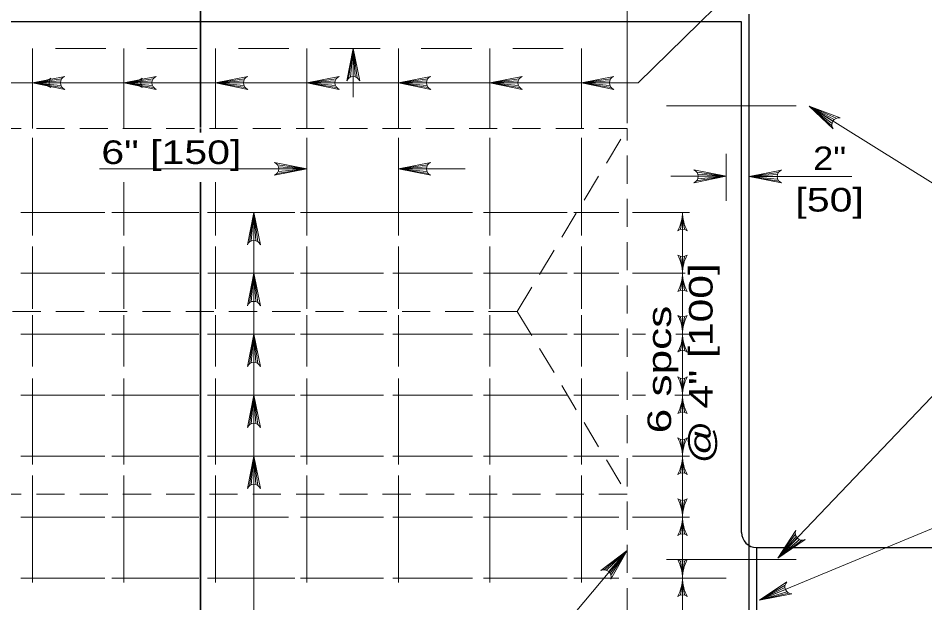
# Model space of a CAD drawing. Extents: x 758.3 to 792.3, y 849.7 to 893.7.
# Drawn here: x 771.26 to 777.25, y 887.19 to 891.06 of the extents above; entities that cross this region are included whole.
import ezdxf
from ezdxf.enums import TextEntityAlignment as Align

# ---------------------------------------------------------------- set-up
doc = ezdxf.new("R2010")
doc.units = 0
doc.header["$LTSCALE"] = 0.062
doc.linetypes.add('MEDIUM_DASHED', pattern=[4.5, 3, -1.5])
doc.layers.add('1', color=7, linetype='Continuous', lineweight=13)

msp = doc.modelspace()

# ---------------------------------------------------------------- linework, layer by layer
at = {"layer": '1', "lineweight": 35}
for p, q in [((772.46325, 891.62983), (772.46325, 890.33417)), ((772.46325, 890.32608), (772.46325, 890.30083)), ((772.46325, 889.97258), (772.46325, 889.61833))]:
    msp.add_line(p, q, dxfattribs=at)
at = {"layer": '1'}
for p, q in [((775.28242, 890.361), (775.28242, 891.18492)), ((771.35175, 890.32608), (771.35175, 890.85517)), ((771.50342, 890.85517), (771.83683, 890.85517)), ((771.9565, 890.32608), (771.9565, 890.85517)), ((772.10817, 890.85517), (772.44158, 890.85517)), ((772.56117, 890.32608), (772.56117, 890.85517)), ((772.71292, 890.85517), (773.04625, 890.85517)), ((773.16592, 890.32608), (773.16592, 890.85517)), ((773.31758, 890.85517), (773.651, 890.85517)), ((773.44208, 890.659), (773.47208, 890.85517)), ((773.45467, 890.66642), (773.47208, 890.85517)), ((773.47208, 890.535), (773.47208, 890.85517)), ((773.47208, 890.66983), (773.47208, 890.85517)), ((773.48583, 890.66783), (773.47208, 890.85517)), ((773.49925, 890.66125), (773.47208, 890.85517)), ((773.77067, 890.32608), (773.77067, 890.85517)), ((773.92233, 890.85517), (774.25575, 890.85517)), ((774.37533, 890.32608), (774.37533, 890.85517)), ((774.527, 890.85517), (774.86042, 890.85517)), ((774.98008, 890.32608), (774.98008, 890.85517)), ((775.35458, 890.62842), (770.14233, 890.62842)), ((771.54567, 890.65558), (771.35175, 890.62842)), ((771.53908, 890.64217), (771.35175, 890.62842)), ((771.53708, 890.62842), (771.35175, 890.62842)), ((771.5405, 890.611), (771.35175, 890.62842)), ((771.54792, 890.59842), (771.35175, 890.62842)), ((772.15042, 890.65558), (771.9565, 890.62842)), ((772.14383, 890.64217), (771.9565, 890.62842)), ((772.14183, 890.62842), (771.9565, 890.62842)), ((772.14525, 890.611), (771.9565, 890.62842)), ((772.15267, 890.59842), (771.9565, 890.62842)), ((772.75508, 890.65558), (772.56117, 890.62842)), ((772.7485, 890.64217), (772.56117, 890.62842)), ((772.7465, 890.62842), (772.56117, 890.62842)), ((772.74992, 890.611), (772.56117, 890.62842)), ((772.75742, 890.59842), (772.56117, 890.62842)), ((773.35983, 890.65558), (773.16592, 890.62842)), ((773.35325, 890.64217), (773.16592, 890.62842)), ((773.35125, 890.62842), (773.16592, 890.62842)), ((773.35467, 890.611), (773.16592, 890.62842)), ((773.36208, 890.59842), (773.16592, 890.62842)), ((773.9645, 890.65558), (773.77067, 890.62842)), ((773.95792, 890.64217), (773.77067, 890.62842)), ((773.95592, 890.62842), (773.77067, 890.62842)), ((773.95942, 890.611), (773.77067, 890.62842)), ((773.96683, 890.59842), (773.77067, 890.62842)), ((774.56925, 890.65558), (774.37533, 890.62842)), ((774.56267, 890.64217), (774.37533, 890.62842)), ((774.56067, 890.62842), (774.37533, 890.62842)), ((774.56408, 890.611), (774.37533, 890.62842)), ((774.5715, 890.59842), (774.37533, 890.62842)), ((775.17392, 890.65558), (774.98008, 890.62842)), ((775.16742, 890.64217), (774.98008, 890.62842)), ((775.16542, 890.62842), (774.98008, 890.62842)), ((775.16883, 890.611), (774.98008, 890.62842)), ((775.17625, 890.59842), (774.98008, 890.62842)), ((775.54233, 890.47725), (776.399, 890.47725)), ((776.64283, 890.37567), (776.48558, 890.47375)), ((776.63658, 890.35908), (776.48558, 890.47375)), ((776.63625, 890.3445), (776.48558, 890.47375)), ((776.65183, 890.38625), (776.48558, 890.47375)), ((776.6645, 890.39417), (776.48558, 890.47375)), ((771.35175, 889.61833), (771.35175, 890.265)), ((773.16592, 889.61833), (773.16592, 890.265)), ((773.77067, 889.61833), (773.77067, 890.265)), ((774.37533, 889.61833), (774.37533, 890.265)), ((774.98008, 889.61833), (774.98008, 890.265)), ((775.9375, 889.849), (775.9375, 890.15992)), ((771.79583, 890.05975), (773.16592, 890.05975)), ((772.96975, 890.02975), (773.16592, 890.05975)), ((772.972, 890.08692), (773.16592, 890.05975)), ((772.97717, 890.04233), (773.16592, 890.05975)), ((772.97858, 890.07342), (773.16592, 890.05975)), ((772.98058, 890.05975), (773.16592, 890.05975)), ((773.9645, 890.08692), (773.77067, 890.05975)), ((773.95792, 890.07342), (773.77067, 890.05975)), ((773.77067, 890.05975), (774.21117, 890.05975)), ((773.95592, 890.05975), (773.77067, 890.05975)), ((773.95942, 890.04233), (773.77067, 890.05975)), ((773.96683, 890.02975), (773.77067, 890.05975)), ((775.57142, 890.0105), (775.9375, 890.0105)), ((775.74133, 889.9805), (775.9375, 890.0105)), ((775.74367, 890.03758), (775.9375, 890.0105)), ((775.74875, 889.99308), (775.9375, 890.0105)), ((775.75017, 890.02417), (775.9375, 890.0105)), ((775.75217, 890.0105), (775.9375, 890.0105)), ((776.28258, 890.0365), (776.08867, 890.00933)), ((776.276, 890.02308), (776.08867, 890.00933)), ((776.08867, 890.00933), (776.76792, 890.00933)), ((776.274, 890.00933), (776.08867, 890.00933)), ((776.27742, 889.99192), (776.08867, 890.00933)), ((776.28492, 889.97942), (776.08867, 890.00933)), ((771.9565, 889.61833), (771.9565, 889.97258)), ((772.56117, 889.61833), (772.56117, 889.97258)), ((771.83008, 889.77183), (771.2755, 889.77183)), ((772.45125, 889.77183), (771.87758, 889.77183)), ((773.0865, 889.77183), (772.50808, 889.77183)), ((772.78558, 889.57567), (772.81558, 889.77183)), ((772.79817, 889.58308), (772.81558, 889.77183)), ((772.81558, 886.85167), (772.81558, 889.77183)), ((772.81558, 889.5865), (772.81558, 889.77183)), ((772.82925, 889.5845), (772.81558, 889.77183)), ((772.84275, 889.57792), (772.81558, 889.77183)), ((773.16592, 889.77183), (773.1235, 889.77183)), ((774.26117, 889.77183), (773.16592, 889.77183)), ((774.88692, 889.77183), (774.33233, 889.77183)), ((775.2285, 889.77183), (774.92967, 889.77183)), ((775.31867, 889.77183), (775.69467, 889.77183)), ((771.35175, 889.13333), (771.35175, 889.54533)), ((771.9565, 889.13333), (771.9565, 889.54533)), ((772.56117, 889.13333), (772.56117, 889.54533)), ((773.16592, 889.13333), (773.16592, 889.54533)), ((773.77067, 889.13333), (773.77067, 889.54533)), ((774.37533, 889.13333), (774.37533, 889.54533)), ((774.98008, 889.13333), (774.98008, 889.54533)), ((776.27875, 887.48392), (778.14217, 889.441)), ((771.83008, 889.36875), (771.2755, 889.36875)), ((772.45125, 889.36875), (771.87758, 889.36875)), ((773.08075, 889.36875), (772.51192, 889.36875)), ((772.78558, 889.17258), (772.81558, 889.36875)), ((772.79817, 889.18), (772.81558, 889.36875)), ((772.81558, 889.18342), (772.81558, 889.36875)), ((772.82925, 889.18142), (772.81558, 889.36875)), ((772.84275, 889.17483), (772.81558, 889.36875)), ((773.67333, 889.36875), (773.1235, 889.36875)), ((774.26117, 889.36875), (773.73492, 889.36875)), ((774.88692, 889.36875), (774.33233, 889.36875)), ((775.2285, 889.36875), (774.92967, 889.36875)), ((775.31867, 889.36875), (775.6655, 889.36875)), ((771.35175, 888.75258), (771.35175, 889.09167)), ((771.9565, 888.75258), (771.9565, 889.09167)), ((772.56117, 888.75258), (772.56117, 889.09167)), ((773.16592, 888.75258), (773.16592, 889.09167)), ((773.77067, 888.75258), (773.77067, 889.09167)), ((774.37533, 888.75258), (774.37533, 889.09167)), ((774.98008, 888.75258), (774.98008, 889.09167)), ((771.83008, 888.96567), (771.2755, 888.96567)), ((772.45125, 888.96567), (771.87758, 888.96567)), ((773.0865, 888.96567), (772.50808, 888.96567)), ((772.78558, 888.76942), (772.81558, 888.96567)), ((772.79817, 888.77692), (772.81558, 888.96567)), ((772.81558, 888.78033), (772.81558, 888.96567)), ((772.82925, 888.77833), (772.81558, 888.96567)), ((772.84275, 888.77175), (772.81558, 888.96567)), ((773.67333, 888.96567), (773.1235, 888.96567)), ((774.26117, 888.96567), (773.73492, 888.96567)), ((774.88692, 888.96567), (774.33233, 888.96567)), ((775.2285, 888.96567), (774.92967, 888.96567)), ((775.31867, 888.96567), (775.40308, 888.96567)), ((775.60392, 888.96567), (775.69142, 888.96567)), ((771.35175, 888.10433), (771.35175, 888.67275)), ((771.9565, 888.10433), (771.9565, 888.67275)), ((772.56117, 888.10433), (772.56117, 888.67275)), ((773.16592, 888.10433), (773.16592, 888.67275)), ((773.77067, 888.10433), (773.77067, 888.67275)), ((774.37533, 888.10433), (774.37533, 888.67275)), ((774.98008, 888.10433), (774.98008, 888.67275)), ((771.83008, 888.5625), (771.2755, 888.5625)), ((772.45125, 888.5625), (771.87758, 888.5625)), ((773.0865, 888.5625), (772.50808, 888.5625)), ((772.78558, 888.36633), (772.81558, 888.5625)), ((772.79817, 888.37375), (772.81558, 888.5625)), ((772.81558, 888.37717), (772.81558, 888.5625)), ((772.82925, 888.37517), (772.81558, 888.5625)), ((772.84275, 888.36867), (772.81558, 888.5625)), ((773.67333, 888.5625), (773.1235, 888.5625)), ((774.26117, 888.5625), (773.73492, 888.5625)), ((774.88692, 888.5625), (774.33233, 888.5625)), ((775.2285, 888.5625), (774.92967, 888.5625)), ((775.31867, 888.5625), (775.40308, 888.5625)), ((775.5975, 888.5625), (775.69467, 888.5625)), ((771.83008, 888.15942), (771.2755, 888.15942)), ((772.45125, 888.15942), (771.87758, 888.15942)), ((773.0865, 888.15942), (772.50808, 888.15942)), ((772.78558, 887.96325), (772.81558, 888.15942)), ((772.79817, 887.97067), (772.81558, 888.15942)), ((772.81558, 887.97408), (772.81558, 888.15942)), ((772.82925, 887.97208), (772.81558, 888.15942)), ((772.84275, 887.9655), (772.81558, 888.15942)), ((773.67333, 888.15942), (773.1235, 888.15942)), ((774.26117, 888.15942), (773.73492, 888.15942)), ((774.88692, 888.15942), (774.33233, 888.15942)), ((775.2285, 888.15942), (774.92967, 888.15942)), ((775.31867, 888.15942), (775.69467, 888.15942)), ((771.35175, 887.32383), (771.35175, 888.03133)), ((771.9565, 887.32383), (771.9565, 888.03133)), ((772.56117, 887.32383), (772.56117, 888.03133)), ((773.16592, 887.32383), (773.16592, 888.03133)), ((773.77067, 887.32383), (773.77067, 888.03133)), ((774.37533, 887.32383), (774.37533, 888.03133)), ((774.98008, 887.32383), (774.98008, 888.03133)), ((771.83008, 887.75633), (771.2755, 887.75633)), ((772.45125, 887.75633), (771.87758, 887.75633)), ((773.045, 887.75633), (772.50808, 887.75633)), ((773.67333, 887.75633), (773.1235, 887.75633)), ((774.26117, 887.75633), (773.73492, 887.75633)), ((774.88692, 887.75633), (774.33233, 887.75633)), ((775.2285, 887.75633), (774.92967, 887.75633)), ((775.31867, 887.75633), (775.69467, 887.75633)), ((776.39408, 887.64217), (776.27875, 887.48392)), ((776.39917, 887.62808), (776.27875, 887.48392)), ((776.40758, 887.61717), (776.27875, 887.48392)), ((776.4225, 887.6075), (776.27875, 887.48392)), ((776.43667, 887.60408), (776.27875, 887.48392)), ((775.13083, 887.40817), (775.28242, 887.53625)), ((775.14517, 887.4055), (775.28242, 887.53625)), ((775.1605, 887.39667), (775.28242, 887.53625)), ((775.16958, 887.38608), (775.28242, 887.53625)), ((775.17533, 887.37233), (775.28242, 887.53625)), ((775.54233, 887.47508), (776.399, 887.47508)), ((771.83008, 887.35325), (771.2755, 887.35325)), ((772.45125, 887.35325), (771.87758, 887.35325)), ((773.0865, 887.35325), (772.50808, 887.35325)), ((773.67333, 887.35325), (773.1235, 887.35325)), ((774.26117, 887.35325), (773.73492, 887.35325)), ((774.88692, 887.35325), (774.33233, 887.35325)), ((775.2285, 887.35325), (774.92967, 887.35325)), ((775.31867, 887.35325), (775.9375, 887.35325)), ((775.64833, 887.35325), (775.64833, 885.88517)), ((776.32608, 887.30617), (776.15767, 887.20633)), ((776.32517, 887.29125), (776.15767, 887.20633)), ((776.32858, 887.27783), (776.15767, 887.20633)), ((776.3385, 887.26308), (776.15767, 887.20633)), ((776.35017, 887.25433), (776.15767, 887.20633))]:
    msp.add_line(p, q, dxfattribs=at)
at = {"layer": '1', "lineweight": 25}
for p, q in [((776.08867, 887.05092), (776.08867, 891.08192)), ((776.03833, 891.0315), (764.95183, 891.0315)), ((776.03833, 887.65558), (776.03833, 891.0315))]:
    msp.add_line(p, q, dxfattribs=at)
at = {"layer": '1', "linetype": 'MEDIUM_DASHED'}
for p, q in [((775.28242, 890.32608), (766.86683, 890.32608)), ((774.55675, 889.11675), (775.28242, 890.32608)), ((775.28242, 887.10125), (775.28242, 890.32608)), ((768.93292, 889.11675), (774.55675, 889.11675)), ((774.55675, 889.11675), (775.28242, 887.9075)), ((775.28242, 887.9075), (765.70775, 887.9075))]:
    msp.add_line(p, q, dxfattribs=at)
at = {"layer": '1'}
for points in [[(775.35458, 890.62842), (776.26983, 891.52542), (776.51467, 891.52542)], [(773.42925, 890.641), (773.47208, 890.85517), (773.51492, 890.641)], [(771.56592, 890.58558), (771.35175, 890.62842), (771.56592, 890.67125)], [(772.17067, 890.58558), (771.9565, 890.62842), (772.17067, 890.67125)], [(772.77533, 890.58558), (772.56117, 890.62842), (772.77533, 890.67125)], [(773.38008, 890.58558), (773.16592, 890.62842), (773.38008, 890.67125)], [(773.98483, 890.58558), (773.77067, 890.62842), (773.98483, 890.67125)], [(774.5895, 890.58558), (774.37533, 890.62842), (774.5895, 890.67125)], [(775.19425, 890.58558), (774.98008, 890.62842), (775.19425, 890.67125)], [(776.64467, 890.32408), (776.48558, 890.47375), (776.69, 890.39675)], [(776.48558, 890.47375), (778.14217, 889.441), (778.45325, 889.441)], [(772.95175, 890.01692), (773.16592, 890.05975), (772.95175, 890.10258)], [(773.98483, 890.01692), (773.77067, 890.05975), (773.98483, 890.10258)], [(775.72333, 889.96767), (775.9375, 890.0105), (775.72333, 890.05333)], [(776.30292, 889.9665), (776.08867, 890.00933), (776.30292, 890.05217)], [(772.77275, 889.55767), (772.81558, 889.77183), (772.85842, 889.55767)], [(775.64833, 889.77183), (775.64833, 889.36875), (775.649, 888.96942), (775.64833, 888.5625), (775.64833, 888.15942), (775.64833, 887.75633), (775.64833, 887.35325)], [(772.77275, 889.15458), (772.81558, 889.36875), (772.85842, 889.15458)], [(772.77275, 888.7515), (772.81558, 888.96567), (772.85842, 888.7515)], [(772.77275, 888.34833), (772.81558, 888.5625), (772.85842, 888.34833)], [(772.77275, 887.94525), (772.81558, 888.15942), (772.85842, 887.94525)], [(776.15767, 887.20633), (777.773, 887.87817), (778.0095, 887.87817)], [(776.45842, 887.60808), (776.27875, 887.48392), (776.39683, 887.66767)], [(775.28242, 887.53625), (774.29892, 886.36058), (773.90367, 886.36058)], [(775.10933, 887.40308), (775.28242, 887.53625), (775.17383, 887.34675)], [(776.37175, 887.24942), (776.15767, 887.20633), (776.33867, 887.32842)]]:
    msp.add_lwpolyline(points, dxfattribs=at)
at = {"layer": '1', "lineweight": 35}
msp.add_lwpolyline([(772.46325, 889.664), (772.46325, 886.0525), (772.46325, 884.85992)], dxfattribs=at)
at = {"layer": '1', "lineweight": 25}
msp.add_lwpolyline([(776.13908, 887.05092), (776.13908, 887.55475), (779.047, 887.55475)], dxfattribs=at)
at = {"layer": '1'}
for centre, start, end in [((771.58324, 890.62847), 112.08782, 247.91395), ((772.18795, 890.62847), 112.08782, 247.91395), ((772.79266, 890.62847), 112.08782, 247.91395), ((773.39738, 890.62847), 112.08782, 247.91395), ((773.47215, 890.6237), 22.08782, 157.91395), ((774.00209, 890.62847), 112.08782, 247.91395), ((774.60681, 890.62847), 112.08782, 247.91395), ((775.21153, 890.62847), 112.08782, 247.91395), ((776.68205, 890.35132), 80.1484, 215.97453), ((772.93445, 890.0598), 292.08605, 67.91218), ((774.00209, 890.0598), 112.08782, 247.91395), ((775.70606, 890.01051), 292.08605, 67.91218), ((776.32017, 890.00941), 112.08782, 247.91395), ((772.81563, 889.54037), 22.08782, 157.91395), ((772.81563, 889.13727), 22.08782, 157.91395), ((772.81563, 888.73417), 22.08782, 157.91395), ((772.81563, 888.33107), 22.08782, 157.91395), ((772.81563, 887.92796), 22.08782, 157.91395), ((776.43963, 887.65035), 158.04343, 293.86956), ((775.13023, 887.36183), 340.96702, 116.79314), ((776.37117, 887.29563), 134.77936, 270.60548)]:
    msp.add_arc(centre, 0.04623, start, end, dxfattribs=at)
for centre, major_axis, ratio, start_param, end_param in [((771.35008, 890.89176), (0.26337, 0), 0.999895, 4.718777, 5.1971336), ((771.51263, 890.62852), (-0.04999, 0), 0.999895, 5.6336903, 6.9326805), ((771.9548, 890.89176), (0.26337, 0), 0.999895, 4.718777, 5.1971336), ((772.11734, 890.62852), (-0.04999, 0), 0.999895, 5.6336903, 6.9326805), ((771.34913, 890.76273), (0.26829, 0.00567), 0.500052, 4.7097602, 5.1482277), ((771.34913, 890.49442), (-0.26829, 0.00567), 0.500052, 4.2768954, 4.7127576), ((771.34903, 890.36021), (0.26836, 0), 0.999895, 1.0914021, 1.5602334), ((771.95385, 890.76273), (0.26829, 0.00567), 0.500052, 4.7097602, 5.1482277), ((771.95385, 890.49442), (-0.26829, 0.00567), 0.500052, 4.2768954, 4.7127576), ((771.95375, 890.36021), (0.26836, 0), 0.999895, 1.0914021, 1.5602334), ((775.38011, 889.77457), (0.26836, 0), 0.999895, 5.8037911, 6.2726224), ((775.51433, 889.77447), (0.00567, 0.26826), 0.500157, 4.2769014, 4.7127635), ((775.91172, 889.77352), (-0.26337, 0), 0.999895, 0.006388, 0.4847446), ((775.78267, 889.77447), (-0.00567, 0.26826), 0.500157, 1.5681617, 2.0066291), ((775.64845, 889.61099), (-0.04999, 0), 0.999895, 4.062894, 5.3618842), ((775.64825, 889.52957), (0.04999, 0), 0.999895, 4.062894, 5.3618842), ((775.38499, 889.36705), (0.26337, 0), 0.999895, 0.006388, 0.4847446), ((775.51403, 889.3661), (-0.00567, 0.26826), 0.500157, 4.7097543, 5.1482217), ((775.78237, 889.3661), (0.00567, 0.26826), 0.500157, 1.1353087, 1.5711709), ((775.91659, 889.366), (-0.26836, 0), 0.999895, 5.8037911, 6.2726224), ((775.38011, 889.37106), (0.26836, 0), 0.999895, 5.8053055, 6.2741368), ((775.51433, 889.37116), (-0.00526, -0.26827), 0.500157, 1.1353085, 1.5711707), ((775.91172, 889.37081), (-0.26337, 0), 0.999895, 0.0079024, 0.486259), ((775.78267, 889.37157), (0.00607, -0.26825), 0.500157, 4.7097541, 5.1482215), ((775.6487, 889.20789), (-0.04999, 0), 0.999895, 4.0644083, 5.3633985), ((775.64861, 889.1303), (0.04999, 0), 0.999895, 4.0644083, 5.3633985), ((775.38559, 888.96738), (0.26337, 0), 0.999895, 0.0079024, 0.486259), ((775.51464, 888.96662), (0.00607, -0.26825), 0.500157, 1.5681614, 2.0066288), ((775.78298, 888.96703), (-0.00526, -0.26827), 0.500157, 4.2769012, 4.7127634), ((775.9172, 888.96713), (-0.26836, 0), 0.999895, 5.8053055, 6.2741368), ((775.38072, 888.97259), (0.26836, 0), 0.999895, 5.8023052, 6.2711365), ((775.51494, 888.97229), (0.00607, 0.26825), 0.500157, 4.2769016, 4.7127637), ((775.91232, 888.97075), (-0.26337, 0), 0.999895, 0.0049021, 0.4832587), ((775.78328, 888.97189), (0.00527, -0.26827), 0.500157, 4.7097545, 5.1482219), ((775.64882, 888.80862), (-0.04999, 0), 0.999895, 4.0614081, 5.3603983), ((775.38498, 888.56124), (0.26337, 0), 0.999895, 0.0049021, 0.4832587), ((775.64849, 888.72337), (0.04999, 0), 0.999895, 4.0614081, 5.3603983), ((775.91659, 888.5594), (-0.26836, 0), 0.999895, 5.8023052, 6.2711365), ((775.51403, 888.5601), (-0.00527, 0.26827), 0.500157, 4.7097545, 5.1482219), ((775.78237, 888.5597), (-0.00607, -0.26825), 0.500157, 4.2769016, 4.7127637), ((775.38011, 888.56526), (0.26836, 0), 0.999895, 5.8037911, 6.2726224), ((775.51433, 888.56516), (0.00567, 0.26826), 0.500157, 4.2769014, 4.7127635), ((775.91172, 888.56421), (-0.26337, 0), 0.999895, 0.006388, 0.4847446), ((775.78267, 888.56516), (-0.00567, 0.26826), 0.500157, 1.5681617, 2.0066291), ((775.64845, 888.40169), (-0.04999, 0), 0.999895, 4.062894, 5.3618842), ((775.64825, 888.32027), (0.04999, 0), 0.999895, 4.062894, 5.3618842), ((775.38499, 888.15775), (0.26337, 0), 0.999895, 0.006388, 0.4847446), ((775.51403, 888.1568), (-0.00567, 0.26826), 0.500157, 4.7097543, 5.1482217), ((775.78237, 888.1568), (0.00567, 0.26826), 0.500157, 1.1353087, 1.5711709), ((775.91659, 888.1567), (-0.26836, 0), 0.999895, 5.8037911, 6.2726224), ((775.38011, 888.16216), (0.26836, 0), 0.999895, 5.8037911, 6.2726224), ((775.51433, 888.16206), (0.00567, 0.26826), 0.500157, 4.2769014, 4.7127635), ((775.91172, 888.16111), (-0.26337, 0), 0.999895, 0.006388, 0.4847446), ((775.78267, 888.16206), (-0.00567, 0.26826), 0.500157, 1.5681617, 2.0066291), ((775.64845, 887.99859), (-0.04999, 0), 0.999895, 4.062894, 5.3618842), ((775.64825, 887.91717), (0.04999, 0), 0.999895, 4.062894, 5.3618842), ((775.38499, 887.75465), (0.26337, 0), 0.999895, 0.006388, 0.4847446), ((775.51403, 887.7537), (-0.00567, 0.26826), 0.500157, 4.7097543, 5.1482217), ((775.78237, 887.7537), (0.00567, 0.26826), 0.500157, 1.1353087, 1.5711709), ((775.91659, 887.75359), (-0.26836, 0), 0.999895, 5.8037911, 6.2726224), ((775.38011, 887.75906), (0.26836, 0), 0.999895, 5.8037911, 6.2726224), ((775.51433, 887.75896), (0.00567, 0.26826), 0.500157, 4.2769014, 4.7127635), ((775.91172, 887.75801), (-0.26337, 0), 0.999895, 0.006388, 0.4847446), ((775.78267, 887.75896), (-0.00567, 0.26826), 0.500157, 1.5681617, 2.0066291), ((775.64845, 887.59549), (-0.04999, 0), 0.999895, 4.062894, 5.3618842), ((775.64825, 887.51407), (0.04999, 0), 0.999895, 4.062894, 5.3618842), ((775.38499, 887.35155), (0.26337, 0), 0.999895, 0.006388, 0.4847446), ((775.51403, 887.35059), (-0.00567, 0.26826), 0.500157, 4.7097543, 5.1482217), ((775.78237, 887.35059), (0.00567, 0.26826), 0.500157, 1.1353087, 1.5711709), ((775.91659, 887.35049), (-0.26836, 0), 0.999895, 5.8037911, 6.2726224), ((775.38011, 887.35596), (0.26836, 0), 0.999895, 5.8037911, 6.2726224), ((775.51433, 887.35586), (0.00567, 0.26826), 0.500157, 4.2769014, 4.7127635), ((775.91172, 887.35491), (-0.26337, 0), 0.999895, 0.006388, 0.4847445), ((775.78267, 887.35586), (-0.00567, 0.26826), 0.500157, 1.5681617, 2.0066291), ((775.64845, 887.19239), (-0.04999, 0), 0.999895, 4.062894, 5.3618842)]:
    msp.add_ellipse(centre, major_axis=major_axis, ratio=ratio, start_param=start_param, end_param=end_param, dxfattribs=at)
at = {"layer": '1', "lineweight": 25}
msp.add_ellipse((776.1391, 887.65555), major_axis=(0.10079, 0), ratio=0.999895, start_param=3.1415928, end_param=4.712389, dxfattribs=at)

# ---------------------------------------------------------------- texts
at = {"layer": '1', "width": 1.3}
msp.add_text('6" [150]', height=0.156, dxfattribs=at).set_placement((771.80733, 890.09183))
at = {"layer": '1'}
for s, width, p in [('2"', 1.15, (776.62083, 890.05133)), ('[50]', 1.3, (776.62092, 889.77733))]:
    msp.add_text(s, height=0.156, dxfattribs=dict(at, width=width)).set_placement(p, align=Align.CENTER)
for s, width, p in [('@ 4" [100]', 1.35, (775.84742, 888.77304)), ('6 spcs ', 1.4, (775.57342, 888.773))]:
    msp.add_text(s, height=0.156, rotation=90, dxfattribs=dict(at, width=width)).set_placement(p, align=Align.CENTER)

doc.saveas('drawing.dxf')
